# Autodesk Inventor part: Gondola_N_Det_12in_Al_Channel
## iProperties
Shininess: 64.0
Length Units: 11272
Angle Units: 11279
Time Units: 11290
Mass Units: 11286
Length Display Precision: 3
Angle Display Precision: 2
Compacted: True
Part Number: Gondola_N_Det_12in_Al_Channel
Document SubType Name: Modeling
Created: 2004-12
Designer: John Blackburn
Material: Aluminum-6061
Description: AL. Assoc. 8" 6061-T6 Channel
Manufacturer: Standard
Standards Organization: Custom
Density: 0.0
Volumn: 0.0
Area: 0.0
PropertySet Name: Model Information
Control State: 0
Master: False
Checked Out: False
Author: John Blackburn
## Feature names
1. Extrusion1
2. Hole1
3. Hole2
4. Hole3
5. Hole4
6. Hole5
7. Hole6
8. Hole8
9. Extrusion2
10. Hole9
